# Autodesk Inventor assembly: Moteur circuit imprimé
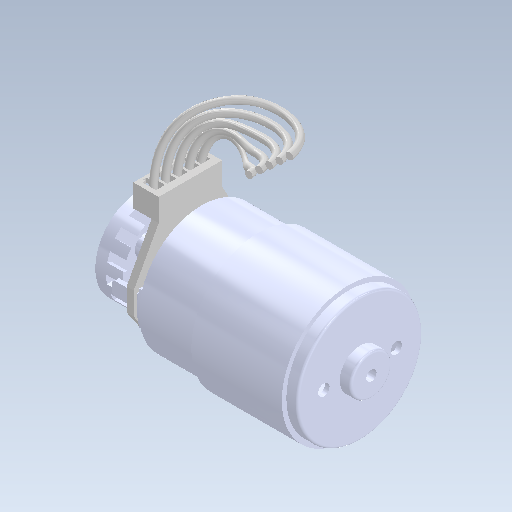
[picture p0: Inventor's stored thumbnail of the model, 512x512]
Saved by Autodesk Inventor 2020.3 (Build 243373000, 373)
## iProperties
Created: 2018-09
Part Number: Moteur circuit imprimé
Document SubType Name: Assembly
Designer: ficho
Mass: 9.13036 g
Surface Area: 124.88 cm^2
Volume: 9.13036 cm^3
Density: 1 g/cm^3
Sending System: SolidWorks 2015
Last Author: adrien
Last Saved: 2019-01-14
Author: ficho
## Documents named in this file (4)
- D:\travail\année 2020-2021\2I2D\laveur de vitre\Lave vitre\4 Dossier Ressources\1 Modèles 3D Solidworks\Moteur circuit imprimé.iam
- D:\travail\année 2020-2021\2I2D\laveur de vitre\Lave vitre\4 Dossier Ressources\1 Modèles 3D Solidworks\Moteur Chenille.ipt
- D:\travail\année 2020-2021\2I2D\laveur de vitre\Lave vitre\4 Dossier Ressources\1 Modèles 3D Solidworks\Circuit Imprimé Moteur.ipt
- D:\travail\année 2020-2021\2I2D\laveur de vitre\Lave vitre\4 Dossier Ressources\1 Modèles 3D Solidworks\Roue Codeur Moteur.ipt
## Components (3 placed, 3 different names)
1. Moteur Chenille:1
2. Circuit Imprimé Moteur:1
3. Roue Codeur Moteur:1
